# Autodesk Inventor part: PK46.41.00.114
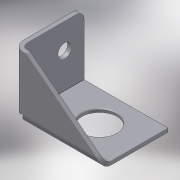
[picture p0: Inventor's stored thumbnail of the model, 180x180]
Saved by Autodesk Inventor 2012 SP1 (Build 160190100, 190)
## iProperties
Created: 2005-07
Part Number: PK46.41.00.114
Material: Steel, Mild
Document SubType Name: Листовой материал
Designer: PVitaliy
Manufacturer: Standard
Standards Organization: Custom
Density: 7.86 g/cm^3
Sheet Metal Rule: По умолчанию
Author: PVitaliy
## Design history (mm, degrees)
node "ФлнОтгиб1"
  sketch "Эскиз2"
    geometry: L1 (0, 0)-(68, 0); L2 (0, 0)-(0, 52)
    constraints: 4 end point, 1 horizontal, 1 vertical, 1 other
    dimensions: "d0" = 68 distance of L1.start L1.end; "d1" = 52 distance of L1.start L2.end
hole "Отверстие1" diameter "d11" = 10.5; stored, may be unused: countersink angle "d15" = 90 deg, drill point angle "d17" = 118 deg; dims "d9" = 15, "d10" = 20, "d12" = 6, "d13" = 4, "d14" = 2, "d16" = 3 (= Толщина)
sketch "Эскиз3"
  geometry: L1 (0, 0)-(-60, 0) reference; L2 (0, 0)-(0, 50) reference; L3 (0, 50)-(-60, 50) reference; L4 (0, 5)-(-58, 50); L5 (-68, 0)-(-68, 50) reference
  constraints: 2 end point, 2 point on line
  dimensions: "d18" = 5 distance from line of L4.start L1; "d19" = 10 distance from line of L4.end L5
feature "Вырез1" sketch "Эскиз3" dims "d20" = 3 (= Толщина), "d21" = 0
node "Фланец1"
feature "Угловое скругление1" dims "d29" = 6
hole "Отверстие2" diameter "d32" = 27; stored, may be unused: countersink angle "d36" = 90 deg, drill point angle "d38" = 118 deg; dims "d30" = 23, "d31" = 30, "d33" = 6, "d34" = 4, "d35" = 2, "d37" = 3 (= Толщина)
feature "Угол1" dims "d39" = 12 (= Размер_высечки), "d40" = 5 (= Радиус_гибки), "d41" = 0.1, "d42" = 0, "Толщина" = 3
chamfer "Фаска1" distance "d43" = 0.5; stored, may be unused: second distance "d44" = 2, angle "d45" = 45 deg
body "Solid1"
feature "Плакирование1" dims "d2" = 50, "d3" = 3 (= Ширина_просечки), "d5" = 6 (= Минимальный_остаток), "d7" = 5 (= Радиус_гибки), "d8" = 3, "Толщина" = 3
feature "Изгиб1" dims "d3" = 3 (= Ширина_просечки), "d4" = 1.5 (= Глубина_просечки), "d5" = 6 (= Минимальный_остаток), "d6" = 5 (= Радиус_гибки), "d7" = 5 (= Радиус_гибки), "d8" = 3, "Толщина" = 3, "Зазор_стыка" = 0.01
sketch "Эскиз4"
  geometry: L1 (60, 0)-(60, 49); L2 (60, 49)-(0, 49); 2 other entities
  constraints: 4 end point, 4 other
feature "Плакирование2" dims "d22" = 3 (= Ширина_просечки), "d24" = 6 (= Минимальный_остаток), "d26" = 49, "d27" = 90 deg, "d28" = 5 (= Радиус_гибки), "Толщина" = 3
feature "Изгиб2" dims "d22" = 3 (= Ширина_просечки), "d23" = 1.5 (= Глубина_просечки), "d24" = 6 (= Минимальный_остаток), "d25" = 5 (= Радиус_гибки), "d26" = 49, "d27" = 90 deg, "d28" = 5 (= Радиус_гибки), "Толщина" = 3, "Зазор_стыка" = 0.01
other parameters: "Радиус_гибки" = 5, "Ширина_просечки" = 3 (= Толщина), "Глубина_просечки" = 1.5 (= 0.5 x Толщина), "Размер_высечки" = 12 (= 4 x Толщина), "Минимальный_остаток" = 6 (= 2 x Толщина), "Радиус_перехода" = 5 (= Радиус_гибки), "JacobiRadiusSize" = 3 (= Толщина), "GapSize" = 3 (= Толщина)
